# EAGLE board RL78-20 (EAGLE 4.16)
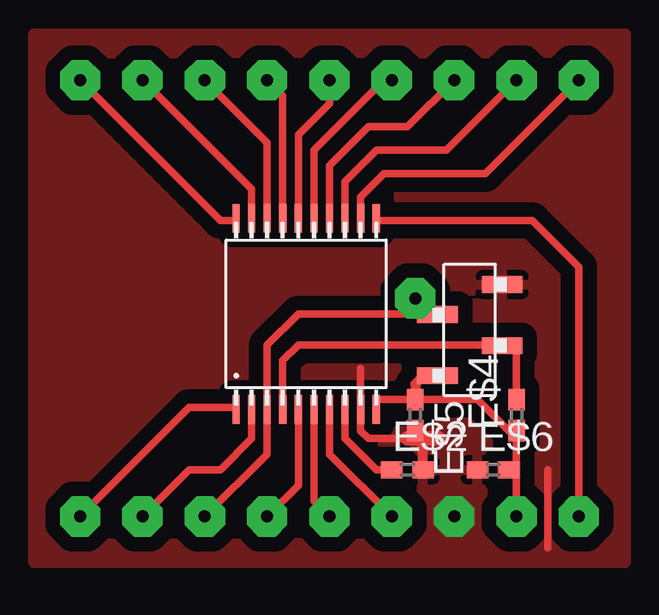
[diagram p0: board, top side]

No outline drawn. Coordinates in mm, seen from the top.
Copper layers (1*16): Top 0.035mm / dielectric 1.5mm / Bottom 0.035mm
Design rules "default": minimum track width 10mil, minimum drill 24mil, track to track 8mil, track to pad 8mil, pad to pad 8mil, via to via 8mil, smd to smd 8mil, copper to edge 40mil, drill to drill 8mil, minimum pad ring 10mil, minimum via ring 8mil, stop-mask expansion 4mil, vias tented up to drill 0mil, thermal gap 10mil

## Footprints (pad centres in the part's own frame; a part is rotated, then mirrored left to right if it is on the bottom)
TSSOP20-RL78 = smd 0.3 x 1.2: P$1 -2.6,-3.981; P$2 -1.95,-3.981; P$3 -1.3,-3.981; P$4 -0.65,-3.981; P$5 0,-3.981; P$6 0.65,-3.981; P$7 1.3,-3.981; P$8 1.95,-3.981; P$9 2.6,-3.981; P$10 3.25,-3.981; P$11 3.25,3.981; P$12 2.6,3.981; P$13 1.95,3.981; P$14 1.3,3.981; P$15 0.65,3.981; P$16 0,3.981; P$17 -0.65,3.981; P$18 -1.3,3.981; P$19 -1.95,3.981; P$20 -2.6,3.981
C0402 = smd 0.9 x 0.7: 1 -0.65,0; 2 0.65,0
HEADERS4 = smd 0.7 x 1.7: P$1 1.27,1.35; P$3 -1.28,1.35; P$4 -0.03,-1.35; P$5 2.52,-1.35

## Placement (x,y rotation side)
E$1  [TSSOP20-RL78]  11.05,10.4 0 top
E$2  [C0402]  15.6,3.9 0 top
E$3  [HEADERS4]  18.2,9.1 90 top
E$4  [C0402]  20.15,6.17 90 top
E$5  [C0402]  15.93,6.17 270 top
E$6  [C0402]  19.18,3.9 0 top

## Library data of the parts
E$1 E$3 = sb
E$2 E$4-E$6 = ref-packages

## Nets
GND: E$2.2 E$3.P$5 E$5.2 E$6.1

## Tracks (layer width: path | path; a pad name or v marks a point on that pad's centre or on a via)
GND  (via drill 0.5 pad 1.68)
  Top 0.305: 13.65,8.12 13.65,5.53 13.97,5.2 15.6,5.2 | 21.45,0.65 21.45,3.9
  Top 0.406: E$2.2 16.25,5.2
  Top 0.61: 15.6,5.2 16.25,5.2 16.9,5.2
  other vias: 17.55,1.95
  pour Top (isolate 0.61): 0,0 0,22.1 24.7,22.1 24.7,0
S$1  (via drill 0.5 pad 1.68)
  other vias: 1.95,1.95
S$2  (via drill 0.5 pad 1.68)
  Top 0.305: v4.55,1.95 6.5,3.9 7.8,3.9 9.1,5.2 9.1,6.5
S$3  (via drill 0.5 pad 1.68)
  Top 0.305: v7.15,1.95 9.75,4.55 9.75,9.1 11.05,10.4 15.93,10.4 | 15.93,10.4 16.9,10.4 | 15.93,10.4 v15.93,11.05
S$4  (via drill 0.5 pad 1.68)
  Top 0.305: v9.75,1.95 11.05,3.25 11.05,6.5
S$5  (via drill 0.5 pad 1.68)
  Top 0.305: v12.35,1.95 11.7,2.6 11.7,6.5
S$6  (via drill 0.5 pad 1.68)
  Top 0.305: 14.3,6.5 14.3,6.83 18.52,6.83 20.15,5.2 v20.15,1.95
S$7
  Top 0.305: 13,6.5 13,5.2 14.3,3.9 14.62,3.9
S$8  (via drill 0.5 pad 1.68)
  Top 0.305: 14.3,14.3 20.8,14.3 22.75,12.35 v22.75,1.95
S$9
  Top 0.406: 15.93,6.83 15.93,7.47 16.25,7.8
S$11  (via drill 0.5 pad 1.68)
  Top 0.305: 13,14.3 13,15.93 14.3,17.23 17.23,17.23 v20.15,20.15
S$12  (via drill 0.5 pad 1.68)
  Top 0.305: 12.35,14.3 12.35,16.57 13.97,18.2 15.6,18.2 v17.55,20.15
S$13  (via drill 0.5 pad 1.68)
  Top 0.305: 11.7,14.95 11.7,17.23 14.62,20.15 v14.95,20.15
S$14  (via drill 0.5 pad 1.68)
  Top 0.305: v12.35,20.15 12.35,19.18 11.05,17.88 11.05,14.3
S$15  (via drill 0.5 pad 1.68)
  Top 0.305: v9.75,20.15 10.4,19.5 10.4,14.3
S$16  (via drill 0.5 pad 1.68)
  Top 0.305: v7.15,20.15 9.75,17.55 9.75,14.95
S$17  (via drill 0.5 pad 1.68)
  Top 0.305: v4.55,20.15 9.1,15.6 9.1,14.3
S$18  (via drill 0.5 pad 1.68)
  Top 0.305: 8.45,14.3 7.8,14.3 v1.95,20.15
S$30  (via drill 0.5 pad 1.68)
  Top 0.305: 13.65,14.3 13.65,15.28 14.62,16.25 18.85,16.25 v22.75,20.15
S$31
  Top 0.305: 8.45,6.5 6.5,6.5 1.95,1.95
S$32
  Top 0.305: 10.4,6.5 10.4,8.45 11.05,9.1 20.15,9.1 20.15,7.15
S$34  (via drill 0.5 pad 1.68)
  Top 0.305: 12.35,6.5 12.35,4.55 v14.95,1.95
